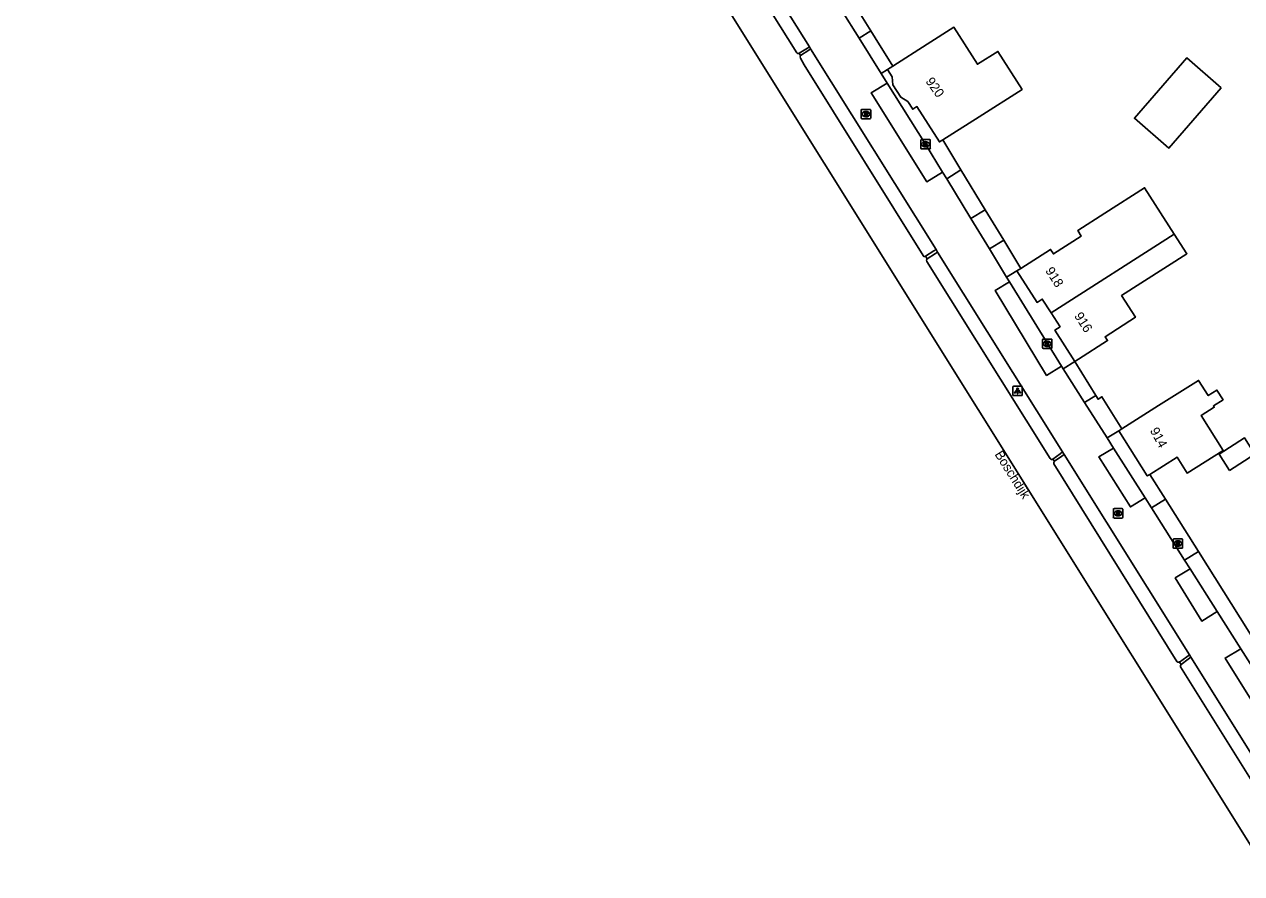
# Model space of a CAD drawing. Extents: x 158461 to 159795, y 387220 to 388672.
# Drawn here: x 158625.6 to 158755, y 387342.1 to 387432.5 of the extents above; entities that cross this region are included whole.
import ezdxf

# ---------------------------------------------------------------- set-up
doc = ezdxf.new("R2010")
doc.units = 0
for name, color, linetype in [('IMGEO_Haag', 7, 'Continuous'), ('IMGEO_Kolk', 7, 'Continuous'), ('IMGEO_Lichtpunt', 7, 'Continuous'), ('IMGEO_Openbare_ruimte_label', 7, 'Continuous'), ('IMGEO_Pand', 7, 'Continuous'), ('IMGEO_Pand_nummerreeks', 7, 'Continuous'), ('IMGEO_Rijbaan_lokaal_open', 7, 'Continuous'), ('IMGEO_Rijbaan_regionaal_gesloten', 7, 'Continuous'), ('IMGEO_Rioolput', 7, 'Continuous'), ('IMGEO_Voetpad_open', 7, 'Continuous')]:
    doc.layers.add(name, color=color, linetype=linetype)

msp = doc.modelspace()

# ---------------------------------------------------------------- linework, layer by layer
at = {"layer": 'IMGEO_Haag'}
for points in [[(158707.96, 387429.41), (158708.86, 387429.96), (158709.06, 387430.09)], [(158709.19, 387429.88), (158708.99, 387429.74), (158708.13, 387429.17)], [(158721.42, 387407.81), (158722.3, 387408.38), (158722.53, 387408.53)], [(158722.7, 387408.26), (158722.47, 387408.11), (158721.6, 387407.54)], [(158734.97, 387386.21), (158735.74, 387386.8), (158735.99, 387386.99)], [(158736.15, 387386.73), (158735.9, 387386.55), (158735.12, 387386)], [(158748.41, 387364.64), (158749.21, 387365.19), (158749.5, 387365.39)], [(158749.64, 387365.16), (158749.36, 387364.95), (158748.6, 387364.38)]]:
    msp.add_lwpolyline(points, dxfattribs=at)
at = {"layer": 'IMGEO_Kolk'}
for p, q in [((158720.92, 387419.31), (158720.92, 387420.16)), ((158721, 387420.23), (158721.85, 387420.23)), ((158721.41, 387420.01), (158721.44, 387420.01)), ((158721.92, 387420.16), (158721.92, 387419.31)), ((158721.85, 387419.23), (158721, 387419.23)), ((158721.43, 387419.45), (158721.41, 387419.45)), ((158733.86, 387398.08), (158733.86, 387398.93)), ((158733.93, 387399), (158734.78, 387399)), ((158734.78, 387398), (158733.93, 387398)), ((158734.37, 387398.22), (158734.34, 387398.22)), ((158734.35, 387398.78), (158734.37, 387398.78)), ((158734.86, 387398.93), (158734.86, 387398.08)), ((158747.76, 387376.82), (158747.76, 387377.67)), ((158747.83, 387377.75), (158748.68, 387377.75)), ((158748.24, 387377.53), (158748.27, 387377.53)), ((158748.76, 387377.67), (158748.76, 387376.82)), ((158748.68, 387376.75), (158747.83, 387376.75)), ((158748.27, 387376.97), (158748.24, 387376.97))]:
    msp.add_line(p, q, dxfattribs=at)
for points in [[(158720.92, 387419.31), (158720.92, 387420.16)], [(158721, 387420.23), (158721.85, 387420.23)], [(158721.24, 387419.93), (158721.37, 387419.93), (158721.37, 387419.78), (158721.5, 387419.93), (158721.66, 387419.93), (158721.51, 387419.78), (158721.67, 387419.53), (158721.51, 387419.53), (158721.43, 387419.7), (158721.37, 387419.63), (158721.37, 387419.53), (158721.24, 387419.53), (158721.24, 387419.93)], [(158721.92, 387420.16), (158721.92, 387419.31)], [(158721.85, 387419.23), (158721, 387419.23)], [(158733.86, 387398.08), (158733.86, 387398.93)], [(158733.93, 387399), (158734.78, 387399)], [(158734.78, 387398), (158733.93, 387398)], [(158734.18, 387398.7), (158734.3, 387398.7), (158734.3, 387398.55), (158734.43, 387398.7), (158734.6, 387398.7), (158734.45, 387398.55), (158734.6, 387398.3), (158734.45, 387398.3), (158734.37, 387398.47), (158734.3, 387398.4), (158734.3, 387398.3), (158734.18, 387398.3), (158734.18, 387398.7)], [(158734.86, 387398.93), (158734.86, 387398.08)], [(158747.76, 387376.82), (158747.76, 387377.67)], [(158747.83, 387377.75), (158748.68, 387377.75)], [(158748.08, 387377.45), (158748.2, 387377.45), (158748.2, 387377.3), (158748.33, 387377.45), (158748.49, 387377.45), (158748.35, 387377.3), (158748.5, 387377.05), (158748.35, 387377.05), (158748.26, 387377.21), (158748.2, 387377.15), (158748.2, 387377.05), (158748.08, 387377.05), (158748.08, 387377.45)], [(158748.76, 387377.67), (158748.76, 387376.82)], [(158748.68, 387376.75), (158747.83, 387376.75)]]:
    msp.add_lwpolyline(points, dxfattribs=at)
for centre, start, end in [((158721, 387420.16), 91.552, 178.448), ((158721, 387420.16), 91.552, 178.448), ((158721.85, 387420.16), 1.552, 88.448), ((158721.85, 387420.16), 1.552, 88.448), ((158721, 387419.31), 181.552, 268.448), ((158721, 387419.31), 181.552, 268.448), ((158721.85, 387419.31), 271.552, 358.448), ((158721.85, 387419.31), 271.552, 358.448), ((158733.93, 387398.93), 91.552, 178.448), ((158733.93, 387398.93), 91.552, 178.448), ((158733.93, 387398.08), 181.552, 268.448), ((158733.93, 387398.08), 181.552, 268.448), ((158734.78, 387398.93), 1.552, 88.448), ((158734.78, 387398.93), 1.552, 88.448), ((158734.78, 387398.08), 271.552, 358.448), ((158734.78, 387398.08), 271.552, 358.448), ((158747.83, 387377.67), 91.552, 178.448), ((158747.83, 387377.67), 91.552, 178.448), ((158748.68, 387377.67), 1.552, 88.448), ((158748.68, 387377.67), 1.552, 88.448), ((158747.83, 387376.82), 181.552, 268.448), ((158747.83, 387376.82), 181.552, 268.448), ((158748.68, 387376.82), 271.552, 358.448), ((158748.68, 387376.82), 271.552, 358.448)]:
    msp.add_arc(centre, 0.0765, start, end, dxfattribs=at)
for centre, major_axis, ratio, start_param, end_param in [((158721.41, 387419.73), (-0.387, 0.002), 0.722429, 4.712389, 7.853982), ((158721.43, 387419.73), (-0.39, 0.002), 0.717154, 1.570796, 4.712389), ((158734.34, 387398.5), (-0.387, 0.002), 0.722429, 4.712389, 7.853982), ((158734.37, 387398.5), (-0.39, 0.002), 0.717154, 1.570796, 4.712389), ((158748.24, 387377.25), (-0.387, 0.002), 0.722429, 4.712389, 7.853982), ((158748.27, 387377.25), (-0.39, 0.002), 0.717154, 1.570796, 4.712389)]:
    msp.add_ellipse(centre, major_axis=major_axis, ratio=ratio, start_param=start_param, end_param=end_param, dxfattribs=at)
at = {"layer": 'IMGEO_Lichtpunt'}
for p, q in [((158731.61, 387393.98), (158730.8, 387393.98)), ((158731.61, 387393.98), (158730.8, 387393.98)), ((158730.71, 387393.89), (158730.71, 387393.08)), ((158730.71, 387393.89), (158730.71, 387393.08)), ((158730.8, 387392.99), (158731.61, 387392.99)), ((158730.8, 387392.99), (158731.61, 387392.99)), ((158731.7, 387393.08), (158731.7, 387393.89)), ((158731.7, 387393.08), (158731.7, 387393.89))]:
    msp.add_line(p, q, dxfattribs=at)
for points in [[(158731.08, 387393.55), (158731.12, 387393.52), (158730.93, 387393.26), (158730.89, 387393.29), (158731.08, 387393.55)], [(158731.18, 387393.5), (158731.23, 387393.5), (158731.23, 387393.18), (158731.18, 387393.18), (158731.18, 387393.5)], [(158731.29, 387393.52), (158731.33, 387393.55), (158731.52, 387393.29), (158731.48, 387393.26), (158731.29, 387393.52)]]:
    msp.add_lwpolyline(points, dxfattribs=at)
msp.add_circle((158731.21, 387393.69), 0.0994, dxfattribs=at)
for centre, start, end in [((158730.8, 387393.89), 90, 180), ((158730.8, 387393.89), 90, 180), ((158731.61, 387393.89), 0, 90), ((158731.61, 387393.89), 0, 90), ((158730.8, 387393.08), 180, 270), ((158730.8, 387393.08), 180, 270), ((158731.61, 387393.08), 270, 0), ((158731.61, 387393.08), 270, 360)]:
    msp.add_arc(centre, 0.0946, start, end, dxfattribs=at)
at = {"layer": 'IMGEO_Pand'}
for points in [[(158717.94, 387428.04), (158721.58, 387430.37), (158724.43, 387432.18), (158726.94, 387428.24), (158729.11, 387429.62), (158731.68, 387425.57), (158727.11, 387422.66), (158723.24, 387420.2)], [(158717.94, 387428.04), (158717.37, 387427.68)], [(158717.37, 387427.68), (158717.86, 387426.91), (158717.95, 387426.05), (158718.79, 387424.73), (158719.53, 387424.28), (158720.05, 387423.46), (158720.49, 387423.75), (158722.89, 387419.98), (158723.24, 387420.2)], [(158752.85, 387425.74), (158747.3, 387419.33), (158743.63, 387422.5), (158749.19, 387428.92), (158752.85, 387425.74)], [(158731.55, 387406.52), (158734.71, 387408.54), (158735.01, 387408.07), (158737.97, 387409.96), (158737.6, 387410.54), (158740.48, 387412.39), (158744.72, 387415.1), (158745.85, 387413.33), (158747.87, 387410.18)], [(158747.87, 387410.18), (158734.78, 387401.79)], [(158747.87, 387410.18), (158749.21, 387408.08), (158742.26, 387403.63), (158743.74, 387401.32), (158740.51, 387399.25), (158740.78, 387398.84), (158737.69, 387396.86), (158737.31, 387396.62)], [(158731.55, 387406.52), (158731.14, 387406.25)], [(158731.14, 387406.25), (158733.28, 387402.91), (158733.83, 387403.26), (158734.78, 387401.79)], [(158734.78, 387401.79), (158735.72, 387400.32), (158735.17, 387399.96), (158737.31, 387396.62)], [(158742.29, 387389.46), (158746.19, 387391.92), (158750.45, 387394.61), (158751.48, 387392.99), (158752.4, 387393.58), (158753.06, 387392.54), (158752.03, 387391.89), (158752.12, 387391.75), (158750.72, 387390.87), (158753.06, 387387.16), (158749.24, 387384.75), (158748.17, 387386.45), (158745.27, 387384.61)], [(158742.29, 387389.46), (158741.96, 387389.25)], [(158741.96, 387389.25), (158744.99, 387384.44), (158745.27, 387384.61)], [(158753.73, 387385.03), (158752.63, 387386.77), (158755.34, 387388.48), (158756.44, 387386.74), (158753.73, 387385.03)]]:
    msp.add_lwpolyline(points, dxfattribs=at)
at = {"layer": 'IMGEO_Rijbaan_lokaal_open'}
for points in [[(158709.06, 387430.09), (158701.74, 387441.8)], [(158714.36, 387431.02), (158710.61, 387437.02)], [(158716.71, 387427.27), (158714.36, 387431.02)], [(158709.19, 387429.88), (158709.06, 387430.09)], [(158722.53, 387408.53), (158709.19, 387429.88)], [(158717.35, 387426.24), (158716.71, 387427.27)], [(158723.23, 387416.77), (158721.55, 387415.74), (158715.63, 387425.2), (158717.35, 387426.24)], [(158723.67, 387416.05), (158723.23, 387416.77)], [(158726.24, 387411.82), (158723.67, 387416.05)], [(158728.21, 387408.6), (158726.24, 387411.82)], [(158722.7, 387408.26), (158722.53, 387408.53)], [(158735.99, 387386.99), (158722.7, 387408.26)], [(158730.04, 387405.59), (158728.21, 387408.6)], [(158735.88, 387396.11), (158734.29, 387395.14), (158728.81, 387404.16), (158730.35, 387405.09)], [(158730.35, 387405.09), (158730.04, 387405.59)], [(158736.06, 387395.83), (158735.88, 387396.11)], [(158738.32, 387392.26), (158736.06, 387395.83)], [(158740.72, 387388.48), (158738.32, 387392.26)], [(158741.39, 387387.41), (158740.72, 387388.48)], [(158735.99, 387386.99), (158736.15, 387386.73)], [(158749.5, 387365.39), (158736.15, 387386.73)], [(158744.77, 387382.1), (158743.21, 387381.14), (158739.85, 387386.49), (158741.39, 387387.41)], [(158745.44, 387381.04), (158744.77, 387382.1)], [(158748.97, 387375.47), (158745.44, 387381.04)], [(158749.57, 387374.54), (158748.97, 387375.47)], [(158752.43, 387370.02), (158750.79, 387369), (158747.98, 387373.59), (158749.57, 387374.54)], [(158754.95, 387366.05), (158752.43, 387370.02)], [(158769.22, 387343.24), (158767.55, 387342.19), (158753.27, 387365.05), (158754.95, 387366.05)], [(158749.64, 387365.16), (158749.5, 387365.39)], [(158763.01, 387343.76), (158749.64, 387365.16)]]:
    msp.add_lwpolyline(points, dxfattribs=at)
at = {"layer": 'IMGEO_Rijbaan_regionaal_gesloten'}
for points in [[(158824.18, 387235.99), (158792.36, 387286.93), (158694.26, 387443.97), (158684.57, 387459.46), (158661.98, 387495.7), (158658.09, 387501.91), (158642.29, 387527.16), (158630.02, 387546.72), (158625.56, 387554.19)], [(158707.71, 387429.45), (158700.61, 387440.85)], [(158708.13, 387429.17), (158707.96, 387429.41)], [(158721.15, 387407.89), (158708.5, 387428.2), (158708.12, 387428.91)], [(158721.6, 387407.54), (158721.42, 387407.81)], [(158734.68, 387386.3), (158721.55, 387407.27)], [(158735.12, 387386), (158734.97, 387386.21)], [(158748.14, 387364.71), (158735.06, 387385.71)], [(158748.6, 387364.38), (158748.41, 387364.64)], [(158761.76, 387343.03), (158761.65, 387343.14), (158748.54, 387364.12)]]:
    msp.add_lwpolyline(points, dxfattribs=at)
for centre, radius, start, end in [((158707.86, 387429.57), 0.194, 218.9084, 300.6837), ((158708.38, 387429.03), 0.285, 151.6861, 205.6598), ((158721.31, 387407.94), 0.166, 197.4348, 309.1268), ((158721.81, 387407.36), 0.28, 140.8072, 198.8098), ((158734.89, 387386.45), 0.256, 216.8081, 288.8467), ((158735.31, 387385.81), 0.262, 134.3918, 201.7495), ((158748.32, 387364.85), 0.227, 216.5785, 293.9755), ((158748.77, 387364.2), 0.244, 135.1479, 200.8741)]:
    msp.add_arc(centre, radius, start, end, dxfattribs=at)
at = {"layer": 'IMGEO_Rioolput'}
for p, q in [((158714.58, 387422.52), (158714.58, 387423.37)), ((158714.65, 387423.44), (158715.5, 387423.44)), ((158715.06, 387423.22), (158715.09, 387423.22)), ((158715.09, 387422.66), (158715.06, 387422.66)), ((158715.58, 387423.37), (158715.58, 387422.52)), ((158715.5, 387422.44), (158714.65, 387422.44)), ((158741.39, 387380.04), (158741.39, 387380.89)), ((158741.46, 387380.96), (158742.32, 387380.96)), ((158742.32, 387379.96), (158741.46, 387379.96)), ((158741.9, 387380.18), (158741.87, 387380.18)), ((158741.88, 387380.74), (158741.9, 387380.74)), ((158742.39, 387380.89), (158742.39, 387380.04))]:
    msp.add_line(p, q, dxfattribs=at)
for points in [[(158714.58, 387422.52), (158714.58, 387423.37)], [(158714.65, 387423.44), (158715.5, 387423.44)], [(158715.16, 387423.14), (158714.91, 387423.14), (158714.91, 387422.74)], [(158714.91, 387422.74), (158715.04, 387422.74), (158715.04, 387422.91), (158715.05, 387422.91)], [(158715.09, 387423.06), (158715.04, 387423.06), (158715.04, 387422.98)], [(158715.04, 387422.98), (158715.09, 387422.98)], [(158715.09, 387422.88), (158715.17, 387422.74), (158715.3, 387422.74), (158715.24, 387422.87)], [(158715.58, 387423.37), (158715.58, 387422.52)], [(158715.5, 387422.44), (158714.65, 387422.44)], [(158741.39, 387380.04), (158741.39, 387380.89)], [(158741.46, 387380.96), (158742.32, 387380.96)], [(158742.32, 387379.96), (158741.46, 387379.96)], [(158741.98, 387380.66), (158741.72, 387380.66), (158741.72, 387380.26)], [(158741.72, 387380.26), (158741.85, 387380.26), (158741.85, 387380.42), (158741.86, 387380.42)], [(158741.9, 387380.58), (158741.85, 387380.58), (158741.85, 387380.5)], [(158741.85, 387380.5), (158741.9, 387380.5)], [(158741.91, 387380.39), (158741.98, 387380.26), (158742.12, 387380.26), (158742.05, 387380.39)], [(158742.39, 387380.89), (158742.39, 387380.04)]]:
    msp.add_lwpolyline(points, dxfattribs=at)
for centre, radius, start, end in [((158714.65, 387423.37), 0.0765, 91.552, 178.448), ((158714.65, 387423.37), 0.0765, 91.552, 178.448), ((158714.65, 387422.52), 0.0765, 181.552, 268.448), ((158714.65, 387422.52), 0.0765, 181.552, 268.448), ((158715.05, 387422.85), 0.0533, 26.0293, 88.6989), ((158715.1, 387422.97), 0.0964, 77.0061, 93.1865), ((158715.07, 387423.17), 0.19, 274.7715, 282.9687), ((158715.11, 387423.02), 0.0378, 276.6634, 79.6772), ((158715.16, 387423.03), 0.109, 350.3612, 89.416), ((158715.16, 387423.03), 0.112, 277.5842, 350.9817), ((158715.15, 387422.82), 0.108, 29.5134, 73.7905), ((158715.5, 387423.37), 0.0765, 1.552, 88.448), ((158715.5, 387423.37), 0.0765, 1.552, 88.448), ((158715.5, 387422.52), 0.0765, 271.552, 358.448), ((158715.5, 387422.52), 0.0765, 271.552, 358.448), ((158741.46, 387380.89), 0.0765, 91.552, 178.448), ((158741.46, 387380.89), 0.0765, 91.552, 178.448), ((158741.46, 387380.04), 0.0765, 181.552, 268.448), ((158741.46, 387380.04), 0.0765, 181.552, 268.448), ((158741.86, 387380.37), 0.0533, 26.0293, 88.6989), ((158741.91, 387380.48), 0.0964, 77.0061, 93.1865), ((158741.89, 387380.69), 0.19, 274.7715, 282.9687), ((158741.92, 387380.54), 0.0378, 276.6634, 79.6772), ((158741.98, 387380.55), 0.109, 350.3612, 89.416), ((158741.97, 387380.55), 0.112, 277.5842, 350.9817), ((158741.96, 387380.33), 0.108, 29.5134, 73.7905), ((158742.31, 387380.89), 0.0765, 1.552, 88.448), ((158742.31, 387380.89), 0.0765, 1.552, 88.448), ((158742.31, 387380.04), 0.0765, 271.552, 358.448), ((158742.31, 387380.04), 0.0765, 271.552, 358.448)]:
    msp.add_arc(centre, radius, start, end, dxfattribs=at)
for centre, major_axis, ratio, start_param, end_param in [((158715.06, 387422.94), (-0.387, 0.002), 0.722429, 4.712389, 7.853982), ((158715.09, 387422.94), (-0.39, 0.002), 0.717154, 1.570796, 4.712389), ((158741.88, 387380.46), (-0.387, 0.002), 0.722429, 4.712389, 7.853982), ((158741.9, 387380.46), (-0.39, 0.002), 0.717154, 1.570796, 4.712389)]:
    msp.add_ellipse(centre, major_axis=major_axis, ratio=ratio, start_param=start_param, end_param=end_param, dxfattribs=at)
at = {"layer": 'IMGEO_Voetpad_open'}
for points in [[(158711.86, 387437.79), (158715.6, 387431.79)], [(158715.6, 387431.79), (158714.36, 387431.02)], [(158715.6, 387431.79), (158716.06, 387431.05), (158717.94, 387428.04)], [(158716.71, 387427.27), (158717.37, 387427.68)], [(158717.35, 387426.24), (158721.42, 387419.73), (158723.23, 387416.77)], [(158723.24, 387420.2), (158725.18, 387417.01)], [(158723.67, 387416.05), (158725.18, 387417.01)], [(158725.18, 387417.01), (158727.76, 387412.76)], [(158726.24, 387411.82), (158727.76, 387412.76)], [(158727.76, 387412.76), (158729.73, 387409.52)], [(158729.73, 387409.52), (158728.21, 387408.6)], [(158729.73, 387409.52), (158731.55, 387406.52)], [(158730.04, 387405.59), (158731.14, 387406.25)], [(158730.35, 387405.09), (158735.88, 387396.11)], [(158736.06, 387395.83), (158737.31, 387396.62)], [(158737.31, 387396.62), (158739.51, 387393.01)], [(158739.51, 387393.01), (158738.32, 387392.26)], [(158739.51, 387393.01), (158739.76, 387392.6), (158740.17, 387392.86), (158742.29, 387389.46)], [(158741.96, 387389.25), (158740.72, 387388.48)], [(158741.39, 387387.41), (158744.77, 387382.1)], [(158745.27, 387384.61), (158746.93, 387381.97)], [(158745.44, 387381.04), (158746.93, 387381.97)], [(158746.93, 387381.97), (158750.44, 387376.4)], [(158750.44, 387376.4), (158748.97, 387375.47)], [(158750.44, 387376.4), (158762.02, 387358)], [(158749.57, 387374.54), (158752.43, 387370.02)], [(158754.95, 387366.05), (158761.19, 387356.23), (158768.71, 387344.05), (158769.22, 387343.24)]]:
    msp.add_lwpolyline(points, dxfattribs=at)

# ---------------------------------------------------------------- texts
at = {"layer": 'IMGEO_Openbare_ruimte_label'}
msp.add_text('Boschdijk', height=1, rotation=302.2119, dxfattribs=at).set_placement((158728.73, 387386.74))
at = {"layer": 'IMGEO_Pand_nummerreeks'}
for s, rotation, p in [('920', 305.6466, (158721.37, 387426.42)), ('918', 302.6498, (158734.11, 387406.28)), ('916', 302.6498, (158737.19, 387401.47)), ('914', 298.2729, (158745.25, 387389.28))]:
    msp.add_text(s, height=1, rotation=rotation, dxfattribs=at).set_placement(p)

doc.saveas('drawing.dxf')
